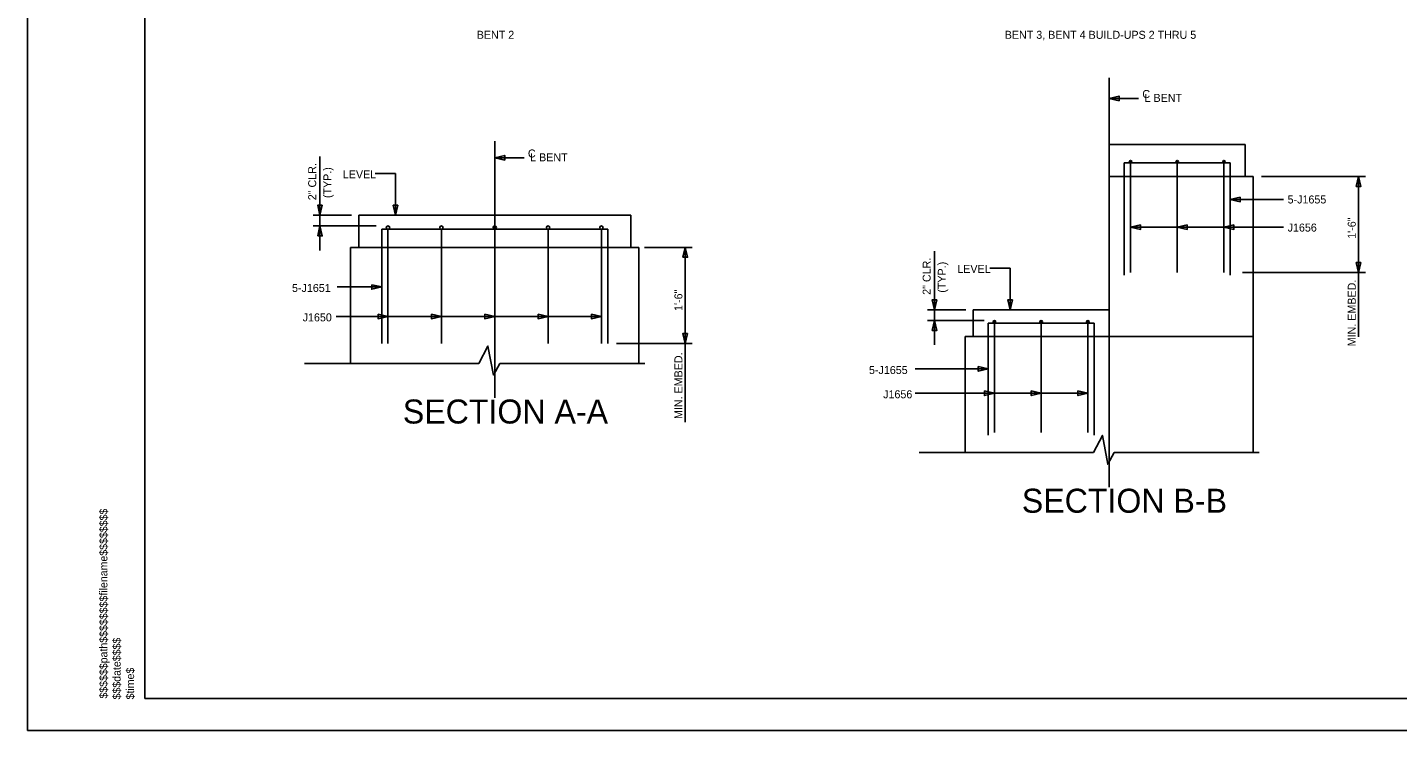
# Model space of a CAD drawing. Extents: x 1970675.2 to 1970711.3, y 796145.2 to 796167.2.
# Drawn here: x 1970675.24 to 1970696.64, y 796145.25 to 796156.23 of the extents above; entities that cross this region are included whole.
import ezdxf

# ---------------------------------------------------------------- set-up
doc = ezdxf.new("R2010")
doc.units = 0
for name, color, linetype in [('BR_AUTO DIMENSION', 7, 'Continuous'), ('BR_BORDER LINES', 7, 'Continuous'), ('BR_CENTER LINES', 7, 'Continuous'), ('BR_CONCRETE', 7, 'Continuous'), ('BR_REBAR', 7, 'Continuous'), ('BR_TEXT', 7, 'Continuous'), ('Default', 7, 'Continuous'), ('Level 31', 7, 'Continuous'), ('RD_SHT_ID', 7, 'Continuous')]:
    doc.layers.add(name, color=color, linetype=linetype)

msp = doc.modelspace()

# ---------------------------------------------------------------- linework, layer by layer
at = {"layer": 'BR_AUTO DIMENSION'}
for p, q in [((1970692.131, 796155.118), (1970692.591, 796155.118)), ((1970679.806, 796154.21), (1970679.806, 796152.745)), ((1970682.535, 796154.19), (1970682.995, 796154.19)), ((1970680.67, 796153.943), (1970680.987, 796153.943)), ((1970680.987, 796153.943), (1970680.987, 796153.293)), ((1970694.509, 796153.898), (1970696.132, 796153.898)), ((1970696.026, 796153.898), (1970696.026, 796151.395)), ((1970694.022, 796153.54), (1970694.856, 796153.54)), ((1970680.296, 796153.293), (1970679.697, 796153.293)), ((1970680.685, 796153.126), (1970679.697, 796153.126)), ((1970692.465, 796153.107), (1970694.853, 796153.107)), ((1970693.194, 796153.107), (1970693.274, 796153.107)), ((1970694.194, 796153.107), (1970694.274, 796153.107)), ((1970684.873, 796152.792), (1970685.616, 796152.792)), ((1970685.51, 796152.792), (1970685.51, 796150.062)), ((1970689.402, 796152.733), (1970689.402, 796151.268)), ((1970690.266, 796152.466), (1970690.583, 796152.466)), ((1970690.583, 796152.466), (1970690.583, 796151.816)), ((1970694.211, 796152.398), (1970696.132, 796152.398)), ((1970680.77, 796152.173), (1970680.075, 796152.173)), ((1970684.202, 796151.714), (1970680.057, 796151.714)), ((1970680.452, 796151.714), (1970680.372, 796151.714)), ((1970681.702, 796151.714), (1970681.622, 796151.714)), ((1970682.535, 796151.714), (1970682.455, 796151.714)), ((1970682.868, 796151.714), (1970682.788, 796151.714)), ((1970683.368, 796151.714), (1970683.288, 796151.714)), ((1970684.202, 796151.714), (1970684.122, 796151.714)), ((1970689.892, 796151.816), (1970689.293, 796151.816)), ((1970690.18, 796151.649), (1970689.293, 796151.649)), ((1970684.436, 796151.292), (1970685.616, 796151.292)), ((1970690.241, 796150.893), (1970689.099, 796150.893)), ((1970691.798, 796150.513), (1970689.099, 796150.513)), ((1970691.069, 796150.513), (1970690.989, 796150.513))]:
    msp.add_line(p, q, dxfattribs=at)
for points in [[(1970692.287, 796155.082), (1970692.131, 796155.118), (1970692.287, 796155.154)], [(1970682.691, 796154.154), (1970682.535, 796154.19), (1970682.691, 796154.226)], [(1970695.99, 796153.742), (1970696.026, 796153.898), (1970696.062, 796153.742)], [(1970694.178, 796153.576), (1970694.022, 796153.54), (1970694.178, 796153.504)], [(1970679.842, 796153.449), (1970679.806, 796153.293), (1970679.77, 796153.449)], [(1970681.023, 796153.449), (1970680.987, 796153.293), (1970680.951, 796153.449)], [(1970679.77, 796152.97), (1970679.806, 796153.126), (1970679.842, 796152.97)], [(1970692.621, 796153.143), (1970692.465, 796153.107), (1970692.621, 796153.071)], [(1970693.35, 796153.143), (1970693.194, 796153.107), (1970693.35, 796153.071)], [(1970694.079, 796153.143), (1970693.923, 796153.107), (1970694.079, 796153.071)], [(1970685.474, 796152.636), (1970685.51, 796152.792), (1970685.546, 796152.636)], [(1970696.062, 796152.554), (1970696.026, 796152.398), (1970695.99, 796152.554)], [(1970680.614, 796152.209), (1970680.77, 796152.173), (1970680.614, 796152.137)], [(1970689.438, 796151.972), (1970689.402, 796151.816), (1970689.366, 796151.972)], [(1970690.619, 796151.972), (1970690.583, 796151.816), (1970690.547, 796151.972)], [(1970680.712, 796151.75), (1970680.868, 796151.714), (1970680.712, 796151.678)], [(1970681.546, 796151.75), (1970681.702, 796151.714), (1970681.546, 796151.678)], [(1970682.379, 796151.75), (1970682.535, 796151.714), (1970682.379, 796151.678)], [(1970683.212, 796151.75), (1970683.368, 796151.714), (1970683.212, 796151.678)], [(1970684.046, 796151.75), (1970684.202, 796151.714), (1970684.046, 796151.678)], [(1970689.366, 796151.493), (1970689.402, 796151.649), (1970689.438, 796151.493)], [(1970685.546, 796151.448), (1970685.51, 796151.292), (1970685.474, 796151.448)], [(1970690.085, 796150.929), (1970690.241, 796150.893), (1970690.085, 796150.857)], [(1970690.183, 796150.549), (1970690.339, 796150.513), (1970690.183, 796150.477)], [(1970690.913, 796150.549), (1970691.069, 796150.513), (1970690.913, 796150.477)], [(1970691.642, 796150.549), (1970691.798, 796150.513), (1970691.642, 796150.477)]]:
    msp.add_lwpolyline(points, close=True, dxfattribs=at)
at = {"layer": 'BR_BORDER LINES'}
for q in [(1970677.07, 796166.746), (1970710.736, 796145.746)]:
    msp.add_line((1970677.07, 796145.746), q, dxfattribs=at)
at = {"layer": 'BR_CENTER LINES'}
for p, q in [((1970692.131, 796155.437), (1970692.131, 796149.049)), ((1970682.535, 796154.451), (1970682.535, 796150.443))]:
    msp.add_line(p, q, dxfattribs=at)
at = {"layer": 'BR_CONCRETE'}
for p, q in [((1970692.131, 796154.399), (1970692.131, 796151.398)), ((1970692.131, 796154.399), (1970694.256, 796154.399)), ((1970694.256, 796154.399), (1970694.256, 796153.898)), ((1970692.131, 796153.898), (1970694.381, 796153.898)), ((1970694.381, 796153.898), (1970694.381, 796151.398)), ((1970680.41, 796153.293), (1970680.41, 796152.792)), ((1970680.41, 796153.293), (1970684.66, 796153.293)), ((1970684.66, 796153.293), (1970684.66, 796152.792)), ((1970680.285, 796152.792), (1970680.285, 796150.98)), ((1970680.285, 796152.792), (1970684.785, 796152.792)), ((1970684.785, 796152.792), (1970684.785, 796150.98)), ((1970690.006, 796151.816), (1970690.006, 796151.398)), ((1970690.006, 796151.816), (1970692.131, 796151.816)), ((1970689.881, 796151.398), (1970689.881, 796149.586)), ((1970689.881, 796151.398), (1970694.381, 796151.398)), ((1970694.381, 796151.398), (1970694.381, 796149.586))]:
    msp.add_line(p, q, dxfattribs=at)
at = {"layer": 'BR_REBAR'}
for p, q in [((1970692.366, 796154.11), (1970692.366, 796152.36)), ((1970692.366, 796154.11), (1970694.022, 796154.11)), ((1970692.465, 796154.149), (1970692.465, 796152.399)), ((1970693.194, 796154.149), (1970693.194, 796152.399)), ((1970693.923, 796154.149), (1970693.923, 796152.399)), ((1970694.022, 796154.11), (1970694.022, 796152.36)), ((1970680.77, 796153.074), (1970680.77, 796151.292)), ((1970684.301, 796153.074), (1970680.77, 796153.074)), ((1970680.868, 796151.292), (1970680.868, 796153.074)), ((1970681.702, 796151.292), (1970681.702, 796153.074)), ((1970682.535, 796151.292), (1970682.535, 796153.074)), ((1970683.368, 796151.292), (1970683.368, 796153.074)), ((1970684.202, 796151.292), (1970684.202, 796153.074)), ((1970684.301, 796153.074), (1970684.301, 796151.292)), ((1970690.241, 796151.61), (1970690.241, 796149.86)), ((1970690.241, 796151.61), (1970691.897, 796151.61)), ((1970690.339, 796151.649), (1970690.339, 796149.899)), ((1970691.069, 796151.649), (1970691.069, 796149.899)), ((1970691.798, 796151.649), (1970691.798, 796149.899)), ((1970691.897, 796151.61), (1970691.897, 796149.86))]:
    msp.add_line(p, q, dxfattribs=at)
for centre, radius in [((1970692.465, 796154.13), 0.0195), ((1970693.194, 796154.13), 0.0195), ((1970693.923, 796154.13), 0.0195), ((1970680.868, 796153.1), 0.0261), ((1970681.702, 796153.1), 0.0261), ((1970682.535, 796153.1), 0.0261), ((1970683.368, 796153.1), 0.0261), ((1970684.202, 796153.1), 0.0261), ((1970690.339, 796151.63), 0.0195), ((1970691.069, 796151.63), 0.0195), ((1970691.798, 796151.63), 0.0195)]:
    msp.add_circle(centre, radius, dxfattribs=at)
at = {"layer": 'Default'}
for p, q in [((1970679.565, 796150.98), (1970682.289, 796150.98)), ((1970682.613, 796150.98), (1970684.88, 796150.98)), ((1970689.161, 796149.586), (1970691.886, 796149.586)), ((1970692.209, 796149.586), (1970694.476, 796149.586))]:
    msp.add_line(p, q, dxfattribs=at)
for points in [[(1970682.613, 796150.98), (1970682.514, 796150.797), (1970682.428, 796151.25), (1970682.289, 796150.98)], [(1970692.209, 796149.586), (1970692.11, 796149.404), (1970692.025, 796149.856), (1970691.886, 796149.586)]]:
    msp.add_lwpolyline(points, dxfattribs=at)
at = {"layer": 'Level 31'}
msp.add_lwpolyline([(1970675.236, 796145.246), (1970711.236, 796145.246), (1970711.236, 796167.246), (1970675.236, 796167.246)], close=True, dxfattribs=at)

# ---------------------------------------------------------------- texts
at = {"layer": 'BR_AUTO DIMENSION'}
for s, p in [('BENT 2', (1970682.254, 796156.048)), ('BENT 3, BENT 4 BUILD-UPS 2 THRU 5', (1970690.5, 796156.048)), ('5-J1655', (1970694.918, 796153.477)), ('J1656', (1970694.918, 796153.038)), ('5-J1655', (1970688.38, 796150.814)), ('J1656', (1970688.601, 796150.435))]:
    msp.add_text(s, height=0.125, dxfattribs=at).set_placement(p)
for s, rotation, p in [('C', 360, (1970692.649, 796155.123)), ('L BENT', 360, (1970692.684, 796155.063)), ('C', 360, (1970683.053, 796154.195)), ('L BENT', 360, (1970683.088, 796154.135)), ('2" CLR.', 90, (1970679.747, 796153.528)), ('(TYP.)', 90, (1970679.984, 796153.561)), ('LEVEL', 360, (1970680.163, 796153.87)), ('1\'-6"', 90, (1970695.982, 796152.925)), ('2" CLR.', 90, (1970689.343, 796152.051)), ('(TYP.)', 90, (1970689.58, 796152.084)), ('LEVEL', 360, (1970689.759, 796152.393)), ('MIN. EMBED.', 90, (1970695.982, 796151.247)), ('5-J1651', 360, (1970679.369, 796152.095)), ('1\'-6"', 90, (1970685.466, 796151.799)), ('J1650', 360, (1970679.535, 796151.636)), ('MIN. EMBED.', 90, (1970685.466, 796150.111))]:
    msp.add_text(s, height=0.125, rotation=rotation, dxfattribs=at).set_placement(p)
at = {"layer": 'BR_TEXT'}
for s, p in [('SECTION A-A', (1970681.1, 796150.041)), ('SECTION B-B', (1970690.767, 796148.648))]:
    msp.add_text(s, height=0.375, rotation=360, dxfattribs=at).set_placement(p)
at = {"layer": 'RD_SHT_ID'}
for s, height, p in [('$$$$$$path$$$$$$$$filename$$$$$$$$', 0.12347, (1970676.486, 796145.746)), ('$$$date$$$$', 0.12347, (1970676.692, 796145.733)), ('$time$', 0.1235, (1970676.903, 796145.733))]:
    msp.add_text(s, height=height, rotation=90, dxfattribs=at).set_placement(p)

doc.saveas('drawing.dxf')
